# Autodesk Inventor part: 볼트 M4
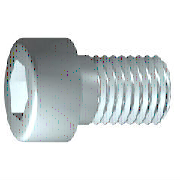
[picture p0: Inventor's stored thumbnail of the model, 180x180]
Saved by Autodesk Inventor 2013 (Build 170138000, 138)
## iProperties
IsCustomPart: 0
Created: 2012-02
Part Number: 볼트 M4
Material: 스테인리스강
Description: 6각 소켓 머리 캡 나사
Document SubType Name: Modeling
Standard: ISO 4762
Designer: mduedu
Standard Revision: Fourth edition 2004-03-01
Standards Organization: ISO
Language: ko-KR
Size Designation: M4 x 12
Categories: <MemberInstance><Categories><Category DisplayName="조임쇠" InternalName="e4da775c-781d-43d5-af7c-5136215cf5a6" Mnemonic="FSTN"><Category DisplayName="볼트" InternalN
Density: 8.08 g/cm^3
Mass: 2.29719 g
Surface Area: 3.30853 cm^2
Volume: 0.284306 cm^3
Author: mduedu
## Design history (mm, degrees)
sketch "스케치1"
  geometry: L1 (-1, 0)-(12, 0); L2 (12, 0)-(12, 2); L3 (12, 2)-(1.75, 2); L4 (1.75, 2)-(1.32, 2); L5 (1.32, 2)-(0, 2); L6 (0, 2)-(0, 3.5); L7 (0, 3.5)-(-4, 3.5); L8 (-4, 3.5)-(-4, 1.732); L9 (-4, 1.732)-(-2, 1.732); L10 (-2, 1.732)-(-1, 0); L11 (-7.2, 0)-(15.2, 0) reference; L12 (0, -0.7)-(0, 4.2) reference; L13 (1.75, 2)-(0, 2)
  constraints: 22 end point, 6 parallel, 2 collinear, 2 perpendicular, 1 horizontal, 1 point on line
  dimensions: "d1" = 10.25 distance from line of L3.end L2 (= GEL); "d2" = 0.42952 distance of L4.end L3.end (computed from GAL); "d3" = 4 distance between parallel lines of L8 L6 (= KOH); "d4" = 2 distance of L8.end L9.end (= INTI); "d5" = 60 deg angle of L10 L1; "d6" = 4 diameter of L3 L1 (= GD); "d7" = 4 diameter of L5 L1 (= BDM); "d8" = 3.4641 diameter of L9 L1 (= 1.1547 x SW); "d9" = 7 diameter of L7 L1 (= KOD); "d26" = 12 distance between parallel lines of L12 L2 (= NLG)
revolve "본체" sketch "스케치1" stored, may be unused: angle "d10" = 90 deg
sketch "스케치2"
  geometry: L1 (0, -4.9)-(0, 4.9) reference; L2 (-4.9, 0)-(4.9, 0) reference; L3 (1.732, 0)-(0.866, -1.5); L4 (0.866, -1.5)-(-0.866, -1.5); L5 (-0.866, -1.5)-(-1.732, 0); L6 (-1.732, 0)-(-0.866, 1.5); L7 (-0.866, 1.5)-(0.866, 1.5); L8 (0.866, 1.5)-(1.732, 0); 2 further points
  constraints: 12 end point, 1 coincident, 1 horizontal alignment, 1 point on line, 12 other
extrude "슬롯" join sketch "스케치2" stored distance "d11" = 10; taper "d12" = 0 deg
workplane "Work Plane1"
fillet "Fillet2" dims "d30" = 0.1 (= R)
body "Solid1"
fillet "모깎기1" dims "d17" = 0.4 (= RR)
feature "스레드" dims "d13" = 10.25 (= GEL), "d14" = 0
chamfer "모따기1" distance "d15" = 0.42941 (= -0.5 x SPD + 0.5 x GD); stored, may be unused: second distance "d16" = 0.42941 (= GUL), angle "d27" = 45 deg
other parameters: "GD" = 4 [user parameter; used in 2 equation terms], "NLG" = 12 [user parameter; used in 1 equation term], "GEL" = 10.25 [user parameter; used in 2 equation terms], "KOD" = 7 [user parameter; used in 1 equation term], "KOH" = 4 [user parameter; used in 1 equation term], "INTI" = 2 [user parameter; used in 1 equation term], "GAL" = 0.42941 (= 0.61345 x PTC) [user parameter; used in 1 equation term], "GUL" = 0.42941 (= 0.61345 x PTC) [user parameter; used in 1 equation term], "BDM" = 4 (= NND) [user parameter; used in 1 equation term], "SW" = 3 [user parameter; used in 2 equation terms], "RR" = 0.4 [user parameter; used in 1 equation term], "SPD" = 3.14117 (= NND - 1.2269 x PTC) [user parameter; used in 1 equation term], "d19" = 0, "d28" = 0, "d29" = 0, "R" = 0.1 [user parameter; used in 1 equation term], "TOA" = 30 deg [user parameter], "GD1" = 3.14117 (= THREADDIA - 1.2269 x PTC) [user parameter], "THREADDIA" = 4 [user parameter; used in 1 equation term], "FAWI" = 45 deg [user parameter], "TPU" = 14.28571 (computed from PTC) [user parameter], "PTC" = 0.7 [user parameter; used in 5 equation terms], "NND" = 4 [user parameter; used in 2 equation terms], "E0" = 3.465 (= 1.155 x SW) [user parameter]
